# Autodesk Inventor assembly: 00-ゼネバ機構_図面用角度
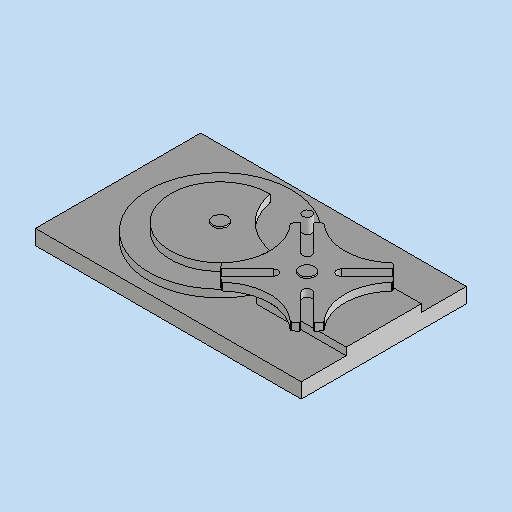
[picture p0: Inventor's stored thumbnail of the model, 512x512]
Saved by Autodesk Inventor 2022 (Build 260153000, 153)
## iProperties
Created: 2021-07
Part Number: 00-ゼネバ機構_図面用角度
Document SubType Name: Assembly
Designer: DesignLab
Author: DesignLab
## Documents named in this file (5)
- d:\Users\DesignLab\Desktop\ver2022\ch04\00-ゼネバ機構_図面用角度.iam
- d:\Users\DesignLab\Desktop\ver2022\ch04\03-ベース板_完成.ipt
- d:\Users\DesignLab\Desktop\ver2022\ch04\01-駆動車_完成.ipt
- d:\Users\DesignLab\Desktop\ver2022\ch04\02-従動車_完成.ipt
- d:\Users\DesignLab\Desktop\ver2022\ch04\04-ピン_完成.ipt
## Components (5 placed, 4 different names)
1. 03-ベース板_完成:1 — 回転:1, 回転:2, 駆動車回転
2. 01-駆動車_完成:1 — 回転:1, フラッシュ:1, 駆動車回転
3. 02-従動車_完成:1 — 回転:2, 回転:3
4. 04-ピン_完成:1 — フラッシュ:1
5. 04-ピン_完成:2 — 回転:3
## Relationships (5: RevoluteJoint 3, Flush 1, Angle 1)
- 回転:1 [RevoluteJoint]: 03-ベース板_完成:1 ↔ 01-駆動車_完成:1
- 回転:2 [RevoluteJoint]: 03-ベース板_完成:1 ↔ 02-従動車_完成:1
- フラッシュ:1 [Flush]: 01-駆動車_完成:1 ↔ 04-ピン_完成:1
- 回転:3 [RevoluteJoint]: 02-従動車_完成:1 ↔ 04-ピン_完成:2
- 駆動車回転 [Angle]: 03-ベース板_完成:1 ↔ 01-駆動車_完成:1
